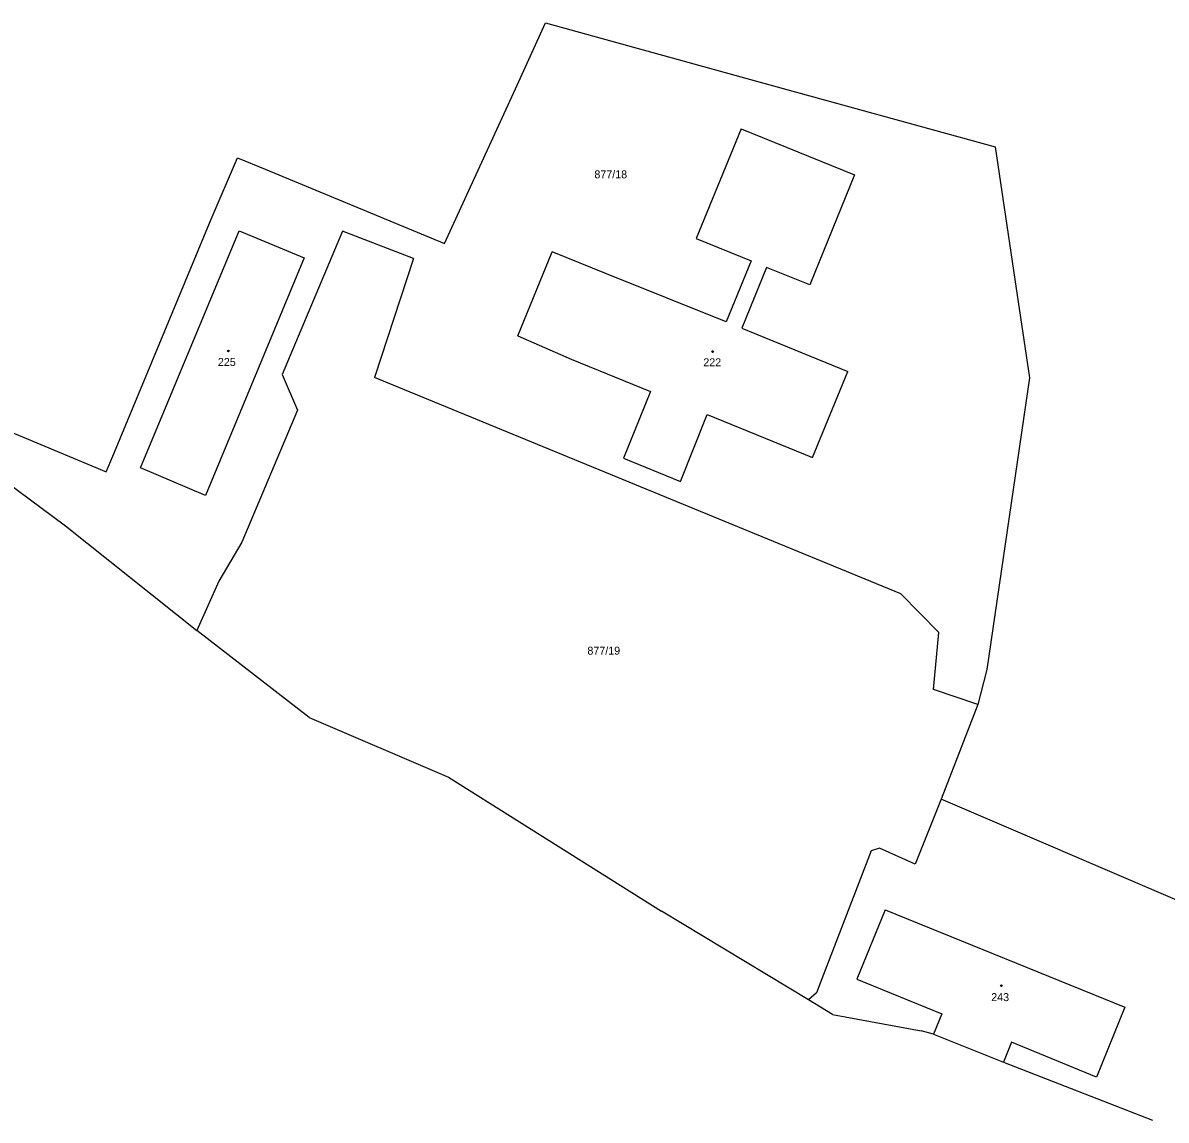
# Model space of a CAD drawing. Extents: x -749173 to -746119, y -1132678 to -1130338.
# Drawn here: x -748525.1 to -748282.3, y -1132628 to -1132395.1 of the extents above; entities that cross this region are included whole.
import ezdxf

# ---------------------------------------------------------------- set-up
doc = ezdxf.new("R2010")
doc.units = 0
for name, color, linetype in [('Vrstva 1', 7, 'Continuous'), ('Vrstva 13', 7, 'Continuous'), ('Vrstva 18', 7, 'Continuous'), ('Vrstva 19', 7, 'Continuous'), ('Vrstva 25', 7, 'Continuous'), ('Vrstva 3', 7, 'Continuous'), ('Vrstva 37', 7, 'Continuous')]:
    doc.layers.add(name, color=color, linetype=linetype)

msp = doc.modelspace()

# ---------------------------------------------------------------- linework, layer by layer
at = {"layer": 'Vrstva 1'}
for points in [[(-748420.5, -1132409.04), (-748414.1, -1132395.06)], [(-748414.1, -1132395.06), (-748368.48, -1132407.62)], [(-748435.54, -1132441.89), (-748420.5, -1132409.04)], [(-748368.48, -1132407.62), (-748318.59, -1132421.35)], [(-748372.55, -1132417.58), (-748382.07, -1132440.87)], [(-748372.55, -1132417.58), (-748348.45, -1132427.35)], [(-748318.59, -1132421.35), (-748314.41, -1132449.54)], [(-748485.08, -1132436.77), (-748479.53, -1132423.69)], [(-748479.53, -1132423.69), (-748473.62, -1132426.14)], [(-748473.62, -1132426.14), (-748435.54, -1132441.89)], [(-748348.45, -1132427.35), (-748357.99, -1132450.71)], [(-748506, -1132487.08), (-748485.08, -1132436.77)], [(-748500.15, -1132489.52), (-748479.18, -1132439.22)], [(-748479.18, -1132439.22), (-748465.37, -1132444.98)], [(-748457.18, -1132439.26), (-748470.02, -1132469.71)], [(-748442.16, -1132445.09), (-748457.18, -1132439.26)], [(-748382.07, -1132440.87), (-748370.45, -1132445.62)], [(-748419.99, -1132461.5), (-748412.72, -1132443.69)], [(-748401.16, -1132448.35), (-748412.72, -1132443.69)], [(-748465.37, -1132444.98), (-748486.34, -1132495.38)], [(-748442.16, -1132445.09), (-748450.44, -1132470.39)], [(-748370.45, -1132445.62), (-748375.72, -1132458.53)], [(-748375.72, -1132458.53), (-748401.16, -1132448.35)], [(-748367.13, -1132446.97), (-748372.4, -1132459.89)], [(-748357.99, -1132450.71), (-748367.13, -1132446.97)], [(-748314.41, -1132449.54), (-748311.31, -1132470.43)], [(-748372.4, -1132459.89), (-748349.9, -1132469.09)], [(-748419.99, -1132461.5), (-748408.63, -1132466.49)], [(-748408.63, -1132466.49), (-748391.78, -1132473.34)], [(-748470.02, -1132469.71), (-748466.77, -1132477.26)], [(-748338.63, -1132516.26), (-748450.44, -1132470.39)], [(-748357.39, -1132487.32), (-748349.9, -1132469.09)], [(-748311.31, -1132470.43), (-748320.35, -1132532.35)], [(-748391.78, -1132473.34), (-748397.51, -1132487.46)], [(-748539.15, -1132477.15), (-748507.38, -1132490.4)], [(-748466.77, -1132477.26), (-748478.57, -1132505.34)], [(-748385.46, -1132492.42), (-748379.78, -1132478.22)], [(-748379.78, -1132478.22), (-748357.39, -1132487.32)], [(-748507.38, -1132490.4), (-748506, -1132487.08)], [(-748397.51, -1132487.46), (-748385.46, -1132492.42)], [(-748486.34, -1132495.38), (-748500.15, -1132489.52)], [(-748478.57, -1132505.34), (-748483.5, -1132513.58)], [(-748483.5, -1132513.58), (-748488.13, -1132524.08)], [(-748330.6, -1132524.5), (-748338.63, -1132516.26)], [(-748331.68, -1132536.57), (-748330.6, -1132524.5)], [(-748320.35, -1132532.35), (-748322.3, -1132539.81)], [(-748322.3, -1132539.81), (-748331.68, -1132536.57)], [(-748322.3, -1132539.81), (-748330.08, -1132559.88)], [(-748330.08, -1132559.88), (-748335.58, -1132573.68)], [(-748279.4, -1132581.64), (-748330.08, -1132559.88)], [(-748344.93, -1132570.87), (-748355.42, -1132598.07)], [(-748343.18, -1132570.3), (-748344.93, -1132570.87)], [(-748335.58, -1132573.68), (-748343.18, -1132570.3)], [(-748341.94, -1132583.37), (-748347.98, -1132598.13)], [(-748341.94, -1132583.37), (-748291.04, -1132604.08)], [(-748355.42, -1132598.07), (-748356.55, -1132601.01)], [(-748347.98, -1132598.13), (-748329.94, -1132605.5)], [(-748356.55, -1132601.01), (-748358.27, -1132602.49)], [(-748291.04, -1132604.08), (-748297.09, -1132618.92)], [(-748329.94, -1132605.5), (-748331.71, -1132609.77)], [(-748315.12, -1132611.5), (-748316.86, -1132615.75)], [(-748297.09, -1132618.92), (-748315.12, -1132611.5)]]:
    msp.add_lwpolyline(points, dxfattribs=at)
at = {"layer": 'Vrstva 13'}
for points in [[(-748541.47, -1132483.03), (-748516.03, -1132501.88)], [(-748516.03, -1132501.88), (-748488.13, -1132524.08)], [(-748464.29, -1132542.54), (-748488.13, -1132524.08)], [(-748464.29, -1132542.54), (-748434.68, -1132555.23)], [(-748434.68, -1132555.23), (-748389.44, -1132583.69)], [(-748358.27, -1132602.49), (-748389.44, -1132583.69)], [(-748353.14, -1132605.58), (-748358.27, -1132602.49)], [(-748353.14, -1132605.58), (-748334.3, -1132609.11)], [(-748331.71, -1132609.77), (-748334.3, -1132609.11)], [(-748331.71, -1132609.77), (-748316.86, -1132615.75)], [(-748316.86, -1132615.75), (-748285.18, -1132628.04)]]:
    msp.add_lwpolyline(points, dxfattribs=at)
at = {"layer": 'Vrstva 25'}
for centre in [(-748481.45, -1132464.72), (-748378.61, -1132464.85), (-748317.29, -1132599.49)]:
    msp.add_circle(centre, 0.175, dxfattribs=at)
at = {"layer": 'Vrstva 3'}
for points in [[(-748372.55, -1132417.58), (-748382.07, -1132440.87)], [(-748372.55, -1132417.58), (-748348.45, -1132427.35)], [(-748348.45, -1132427.35), (-748357.99, -1132450.71)], [(-748500.15, -1132489.52), (-748479.18, -1132439.22)], [(-748479.18, -1132439.22), (-748465.37, -1132444.98)], [(-748382.07, -1132440.87), (-748370.45, -1132445.62)], [(-748419.99, -1132461.5), (-748412.72, -1132443.69)], [(-748401.16, -1132448.35), (-748412.72, -1132443.69)], [(-748465.37, -1132444.98), (-748486.34, -1132495.38)], [(-748370.45, -1132445.62), (-748375.72, -1132458.53)], [(-748375.72, -1132458.53), (-748401.16, -1132448.35)], [(-748367.13, -1132446.97), (-748372.4, -1132459.89)], [(-748357.99, -1132450.71), (-748367.13, -1132446.97)], [(-748372.4, -1132459.89), (-748349.9, -1132469.09)], [(-748419.99, -1132461.5), (-748408.63, -1132466.49)], [(-748408.63, -1132466.49), (-748391.78, -1132473.34)], [(-748357.39, -1132487.32), (-748349.9, -1132469.09)], [(-748391.78, -1132473.34), (-748397.51, -1132487.46)], [(-748385.46, -1132492.42), (-748379.78, -1132478.22)], [(-748379.78, -1132478.22), (-748357.39, -1132487.32)], [(-748397.51, -1132487.46), (-748385.46, -1132492.42)], [(-748486.34, -1132495.38), (-748500.15, -1132489.52)], [(-748341.94, -1132583.37), (-748347.98, -1132598.13)], [(-748341.94, -1132583.37), (-748291.04, -1132604.08)], [(-748347.98, -1132598.13), (-748329.94, -1132605.5)], [(-748291.04, -1132604.08), (-748297.09, -1132618.92)], [(-748329.94, -1132605.5), (-748331.71, -1132609.77)], [(-748331.71, -1132609.77), (-748316.86, -1132615.75)], [(-748315.12, -1132611.5), (-748316.86, -1132615.75)], [(-748297.09, -1132618.92), (-748315.12, -1132611.5)]]:
    msp.add_lwpolyline(points, dxfattribs=at)
at = {"layer": 'Vrstva 37'}
for centre in [(-748481.45, -1132464.72), (-748378.61, -1132464.85), (-748317.29, -1132599.49)]:
    msp.add_circle(centre, 0.175, dxfattribs=at)

# ---------------------------------------------------------------- texts
at = {"layer": 'Vrstva 18'}
for s, p in [('877/18', (-748403.72, -1132428.07)), ('877/19', (-748405.2, -1132529.21))]:
    msp.add_text(s, height=1.7, dxfattribs=at).set_placement(p)
at = {"layer": 'Vrstva 19'}
for s, p in [('225', (-748483.68, -1132467.91)), ('222', (-748380.59, -1132467.98)), ('243', (-748319.44, -1132602.77))]:
    msp.add_text(s, height=1.7, dxfattribs=at).set_placement(p)

doc.saveas('drawing.dxf')
